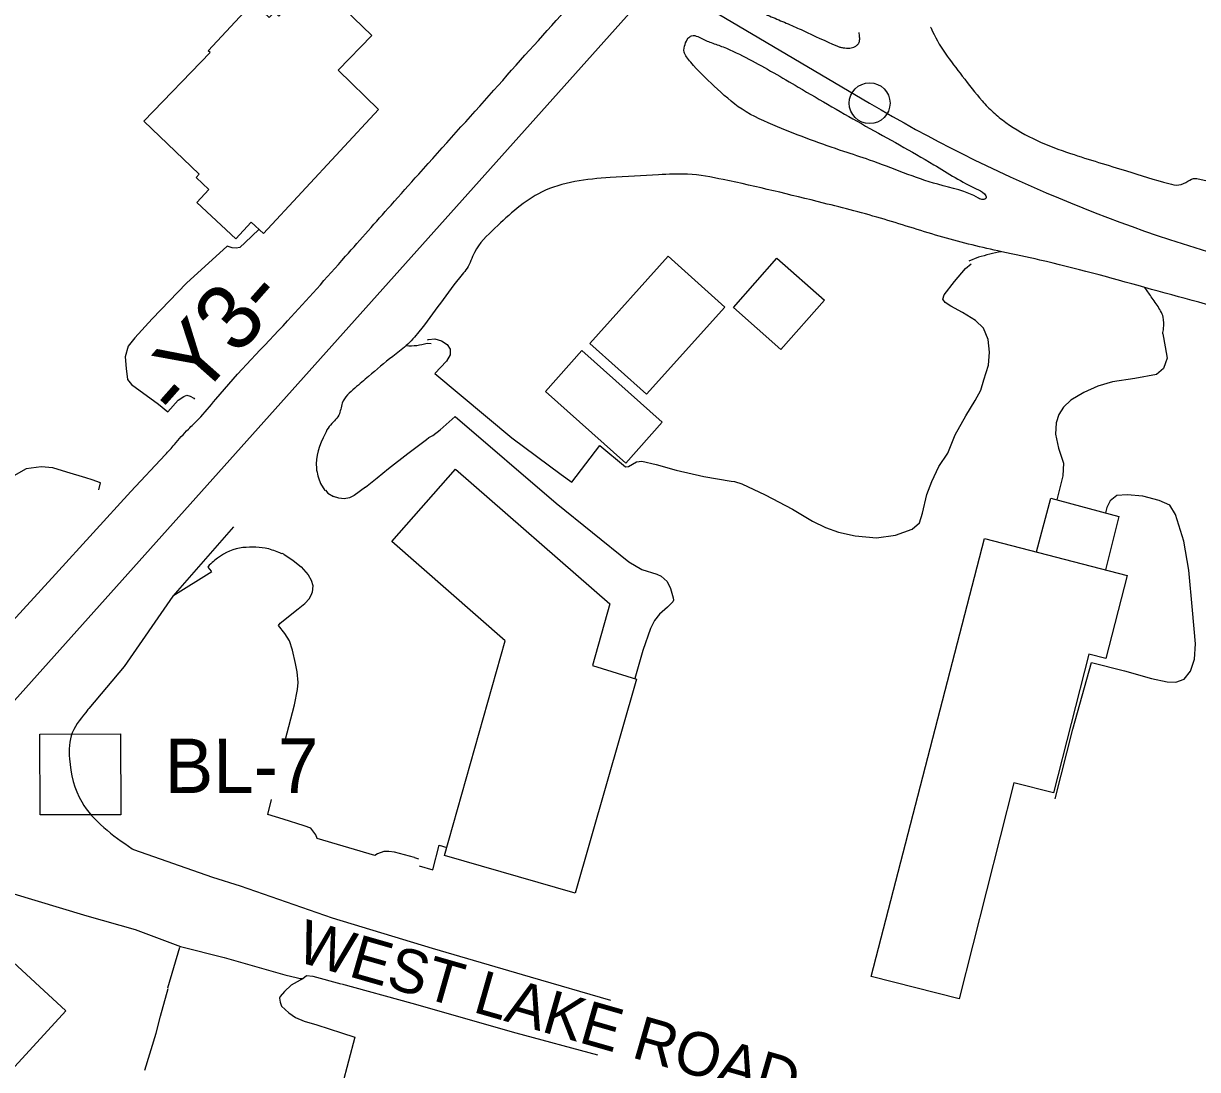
# Model space of a CAD drawing. Extents: x 2088830 to 2093930, y 861854 to 865154.
# Drawn here: x 2091682.1 to 2092113.5, y 863511.1 to 863895.4 of the extents above; entities that cross this region are included whole.
import ezdxf

# ---------------------------------------------------------------- set-up
doc = ezdxf.new("R2010")
doc.units = 0
for name, color, linetype in [('Default', 7, 'Continuous'), ('Exist Building', 7, 'Continuous'), ('Exist Building Metal Canopy', 7, 'Continuous'), ('Exist Horizontal Alignment', 7, 'Continuous'), ('Exist Horizontal Alignment Station Label', 7, 'Continuous'), ('Exist Other Culture Area Outline', 7, 'Continuous'), ('Exist Roads EOP', 7, 'Continuous'), ('Exist Roads EOP Other', 7, 'Continuous'), ('Exist Roads EOP Text', 7, 'Continuous'), ('Exist Roads Soil', 7, 'Continuous')]:
    doc.layers.add(name, color=color, linetype=linetype)

msp = doc.modelspace()

# ---------------------------------------------------------------- linework, layer by layer
at = {"layer": 'Default'}
for p, q in [((2091668.57, 863635.39), (2092319.98, 864363.19)), ((2091898.12, 863922.18), (2091993.02, 863866.1)), ((2091702.85, 863619.58), (2091702.85, 863619.58))]:
    msp.add_line(p, q, dxfattribs=at)
msp.add_lwpolyline([(2091688.1, 863634.33), (2091717.75, 863634.43), (2091717.86, 863604.73), (2091688.21, 863604.63)], close=True, dxfattribs=at)
msp.add_arc((2092280.46, 864352.52), 565, 239.4206, 255.1718, dxfattribs=at)
at = {"layer": 'Exist Building'}
for points in [[(2091812.53, 863863.75), (2091770.26, 863818.18), (2091765.75, 863822.36), (2091760.12, 863816.27), (2091745.73, 863829.61), (2091750.24, 863834.41), (2091745.59, 863838.86), (2091746.7, 863840.03), (2091726.37, 863859.45), (2091750.65, 863884.73), (2091749.93, 863885.4), (2091766.52, 863903.07), (2091772.43, 863897.53), (2091774.3, 863899.52), (2091775.9, 863898.02), (2091785.95, 863908.72), (2091787.07, 863907.67), (2091789.91, 863910.58), (2091810.11, 863890.93), (2091797.71, 863878.18)], [(2091919.05, 863809.88), (2091890.26, 863777.85), (2091911.05, 863759.16), (2091939.84, 863791.19)], [(2091958.97, 863809.2), (2091976.47, 863793.71), (2091960.45, 863775.62), (2091942.96, 863791.11)], [(2091836.79, 863589.79), (2091859.1, 863668.55), (2091817.48, 863705.04), (2091840.86, 863731.69), (2091897.5, 863682.15), (2091891.15, 863659.52), (2091907.32, 863654.52), (2091884.79, 863575.86)], [(2091993.59, 863545.26), (2092035.21, 863706.21), (2092087.71, 863692.63), (2092079.81, 863662.09), (2092073.58, 863663.69), (2092060.58, 863612.8), (2092045.99, 863616.49), (2092025.87, 863537.08)], [(2091665.32, 863562.47), (2091612.57, 863505.19), (2091635.21, 863484.35), (2091646.25, 863496.33), (2091655.98, 863487.38), (2091697.69, 863532.68)]]:
    msp.add_lwpolyline(points, close=True, dxfattribs=at)
at = {"layer": 'Exist Building Metal Canopy'}
msp.add_lwpolyline([(2091887.31, 863775.24), (2091916.83, 863748.91), (2091903.38, 863733.83), (2091873.86, 863760.16)], close=True, dxfattribs=at)
msp.add_lwpolyline([(2092054.4, 863701.24), (2092059.59, 863721), (2092084.65, 863714.28), (2092079.7, 863694.7)], dxfattribs=at)
at = {"layer": 'Exist Horizontal Alignment Station Label'}
msp.add_circle((2091993.02, 863866.1), 7.5, dxfattribs=at)
at = {"layer": 'Exist Other Culture Area Outline'}
msp.add_lwpolyline([(2091827.47, 863585.95), (2091832.54, 863584.48), (2091834.86, 863593.54), (2091837.63, 863592.74)], dxfattribs=at)
at = {"layer": 'Exist Roads EOP'}
for p, q in [((2092032.99, 863809.49), (2092029.47, 863808.1)), ((2091791.23, 863726.41), (2091792.78, 863723.88)), ((2091751.27, 863693.96), (2091736.99, 863684.95))]:
    msp.add_line(p, q, dxfattribs=at)
for points in [[(2091734.18, 863736.92), (2091721.57, 863723.4), (2091693.87, 863693.03), (2091676.72, 863674.36), (2091660.52, 863656.21), (2091640.2, 863634.61)], [(2091759.26, 863710.48), (2091736.93, 863685), (2091719.03, 863659.13), (2091706.08, 863643.77)], [(2091750.38, 863696.42), (2091749.83, 863695.62), (2091751.09, 863694.17)], [(2091721.97, 863592.19), (2091722.52, 863591.93), (2091751.6, 863581.73), (2091761.71, 863578.54), (2091795.52, 863566.8), (2091832.3, 863555.65), (2091868.27, 863545.16), (2091897.82, 863536.6)], [(2091655.69, 863579.19), (2091656.21, 863579.4), (2091656.13, 863579.68), (2091658.97, 863580.88), (2091659.28, 863581.75), (2091666.09, 863580.15), (2091666.95, 863578.98), (2091677.33, 863575.99), (2091705.32, 863567.54), (2091723.14, 863562.53), (2091739.84, 863556.32), (2091755.83, 863552.33), (2091778.96, 863545.71)], [(2091779.25, 863545.61), (2091783.78, 863544.54), (2091784.79, 863544.51), (2091786.06, 863545.62), (2091788.39, 863545.44), (2091798.68, 863542.59)], [(2091784.81, 863544.41), (2091784.75, 863544.39), (2091783.75, 863543.97)], [(2091893.11, 863516.4), (2091863.13, 863524.5), (2091824.96, 863535.32), (2091799.13, 863542.51)]]:
    msp.add_lwpolyline(points, dxfattribs=at)
msp.add_ellipse((2092048.83, 863770.86), major_axis=(-56.28, -10.97), ratio=0.721384, start_param=4.703784, end_param=4.855195, dxfattribs=at)
for points in [[(2091734.18, 863736.92), (2091737.57, 863740.74), (2091742.7, 863746.41), (2091746.39, 863749.99), (2091752.74, 863757.34), (2091779.15, 863786.15), (2091800.43, 863809.86), (2091817.14, 863828.66), (2091827.31, 863840.06), (2091854.93, 863870.83), (2091881.2, 863900.12), (2091888.17, 863907.69), (2091904.65, 863926.31), (2091929.6, 863954.75), (2091942.38, 863969.24), (2091969.89, 863999.82), (2091984.53, 864016.32), (2091999.97, 864033.43), (2092012.73, 864047.99), (2092025.65, 864062.7), (2092046.42, 864086.24), (2092066.29, 864109.17), (2092073.24, 864116), (2092075.7, 864118.27)], [(2091940.52, 863905.82), (2091946.75, 863902.64), (2091952.13, 863900.03), (2091957.58, 863897.59), (2091963.08, 863895.22), (2091965.82, 863894.02), (2091968.55, 863892.81), (2091980.94, 863887.15), (2091982.08, 863886.73), (2091983.28, 863886.46), (2091984.5, 863886.34), (2091985.11, 863886.33), (2091985.7, 863886.36), (2091987.76, 863886.97), (2091988.62, 863887.62), (2091988.95, 863888.04), (2091989.07, 863888.27), (2091989.18, 863888.52), (2091989.3, 863888.97), (2091989.36, 863890.31), (2091989.26, 863891.21), (2091989.14, 863892.1)], [(2091934.8, 863888.35), (2091932.8, 863889.15), (2091929.91, 863890.55), (2091927.6, 863890.89), (2091926.35, 863889.96), (2091925.2, 863887.71), (2091924.87, 863884.91), (2091925.75, 863883.14), (2091927.27, 863881.15), (2091935.92, 863872.36), (2091946.13, 863863.88), (2091959.14, 863857.42), (2091983.53, 863848.38), (2091993, 863845.22), (2092018.13, 863836.3), (2092033.08, 863831.22), (2092034.67, 863830.67), (2092035.87, 863831.32), (2092035.2, 863832.76), (2092032.22, 863834.64), (2092016.56, 863843.52), (2091991.56, 863857.72), (2091966.77, 863872.02), (2091948.66, 863882.32), (2091939.19, 863886.75), (2091934.8, 863888.35)], [(2092015.44, 863894.03), (2092015.59, 863893.68), (2092020.78, 863884.51), (2092027.07, 863876.03), (2092034.41, 863866.92), (2092038.45, 863862.77), (2092043.03, 863859.05), (2092054.59, 863852.38), (2092066.89, 863847.63), (2092087.45, 863841.22), (2092102.98, 863836.55), (2092106.69, 863836.06), (2092109.98, 863837.49), (2092112.72, 863838.5), (2092113.8, 863838.36), (2092114.88, 863838.1), (2092117.05, 863837.51), (2092123.9, 863835.78), (2092134.51, 863833.26), (2092139.82, 863831.98), (2092142.46, 863831.29), (2092145.09, 863830.56), (2092148.56, 863828.9), (2092151.83, 863826.8), (2092157.4, 863823.44), (2092159.85, 863822.5), (2092162.31, 863821.63), (2092167.27, 863820.07), (2092177.32, 863817.44), (2092192.54, 863813.99), (2092197.6, 863812.76), (2092205.33, 863810.83), (2092213.09, 863809.05), (2092215.67, 863809.19), (2092216.97, 863809.43), (2092218.26, 863809.49), (2092229.44, 863807.44), (2092234.76, 863805.43), (2092239.98, 863803.33), (2092250.45, 863799.3), (2092264.32, 863794.54)], [(2092264.79, 863753.35), (2092261.51, 863754.31), (2092220.59, 863764.86), (2092181.43, 863775.4), (2092144.63, 863785.3), (2092133.89, 863787.86), (2092094.14, 863798.41), (2092055.58, 863808.48), (2092041.55, 863811.54), (2092019.95, 863816.88), (2091998.39, 863823.46), (2091976.08, 863829.41), (2091939.23, 863838.04), (2091926.12, 863840.01), (2091915.42, 863839.78), (2091897.67, 863838.81), (2091872.49, 863833.46), (2091855.35, 863820.22), (2091847.81, 863811.29), (2091845.08, 863805.49), (2091843.31, 863803.2), (2091827.39, 863782.15), (2091822.71, 863777.04), (2091817.76, 863773.1), (2091808.91, 863765.73), (2091803.88, 863761.45), (2091799.23, 863755.93), (2091797.96, 863751.49), (2091794.46, 863747.35), (2091792.91, 863744.7), (2091789.71, 863731.97), (2091791.23, 863726.41)], [(2091777.12, 863700.57), (2091775.95, 863701.04), (2091770.93, 863702.64), (2091766.34, 863702.97), (2091761.42, 863702.66), (2091752.44, 863698.22), (2091750.38, 863696.42)], [(2091706.08, 863643.77), (2091705.74, 863643.32), (2091700.03, 863634.86), (2091699.01, 863625.24), (2091703.48, 863609.45), (2091721.97, 863592.19)]]:
    msp.add_spline(points, degree=3, dxfattribs=at)
at = {"layer": 'Exist Roads EOP Other'}
for p, q in [((2091825.76, 863588.95), (2091827.25, 863588.47)), ((2091735.18, 863541.1), (2091739.55, 863556.07))]:
    msp.add_line(p, q, dxfattribs=at)
for points in [[(2091768.62, 863819.7), (2091763.55, 863814.89), (2091761.58, 863813.15), (2091760.27, 863812.8), (2091758.72, 863813.01), (2091756.99, 863813.54), (2091741.95, 863799.94), (2091729.42, 863786.83), (2091722.99, 863779.87), (2091720.52, 863776.85), (2091719.51, 863772.99), (2091719.88, 863768.64), (2091720.26, 863764.58), (2091721.72, 863762.72), (2091731.7, 863755.51), (2091735.11, 863752.76), (2091738.97, 863756.97), (2091741.02, 863758.4), (2091742.11, 863758.89), (2091743.4, 863758.5), (2091744.67, 863757.75), (2091744.93, 863757.36)], [(2091832.48, 863744.09), (2091835.19, 863746.16), (2091840.74, 863750.96), (2091877.82, 863719.2), (2091904.55, 863697.67), (2091909.31, 863694.82), (2091914.77, 863693.12), (2091916.43, 863692.41), (2091918.62, 863690.44), (2091919.81, 863687.77), (2091920.83, 863684.36), (2091921.01, 863683.51), (2091920.66, 863682.93), (2091918.76, 863680.96), (2091915.78, 863678.43), (2091913.91, 863676.07), (2091912.45, 863673.16), (2091909.69, 863665.11), (2091906.7, 863654.71)], [(2091709.82, 863724.09), (2091710.43, 863726.63), (2091707.29, 863727.77), (2091704.98, 863728.48), (2091698.04, 863730.61), (2091692.89, 863732.2), (2091688.54, 863732.52), (2091683.12, 863731.81), (2091676.84, 863728.24), (2091672.3, 863728.53), (2091666.84, 863731.92), (2091655.29, 863742.21), (2091639.69, 863728.05), (2091623.47, 863710.19), (2091631.13, 863703.58), (2091632.8, 863702.2), (2091632.89, 863700.81), (2091632.16, 863698.88), (2091631.56, 863698.16), (2091640.02, 863690.43), (2091637.25, 863687.26), (2091635.22, 863686.33), (2091632.8, 863686.46), (2091631.33, 863687.59)], [(2091807.74, 863725.09), (2091812.05, 863728.54), (2091816.17, 863731.91), (2091823.36, 863737.45), (2091830.21, 863742.59), (2091831.05, 863743.26), (2091832.48, 863744.09)], [(2091793.02, 863724), (2091793.92, 863722.86), (2091796.04, 863721.6)], [(2091807.74, 863725.09), (2091803.63, 863721.95), (2091801.9, 863721.11), (2091799.97, 863720.8), (2091797.94, 863721), (2091796.04, 863721.6)], [(2091777.82, 863700.43), (2091777.18, 863700.72)], [(2091777.82, 863700.43), (2091781.22, 863698.17), (2091784.11, 863695.79), (2091786.67, 863692.84), (2091787.84, 863690.93), (2091788.36, 863688.93), (2091788.12, 863686.37)], [(2091776.44, 863675.04), (2091782.98, 863680.34), (2091785.48, 863682.37), (2091787.14, 863684.21), (2091788.01, 863685.93), (2091788.12, 863686.37)], [(2091778.22, 863631.95), (2091781.62, 863645.11), (2091782.76, 863650.72), (2091783.01, 863653.3), (2091782.68, 863657.18), (2091782.07, 863660.32), (2091781, 863665.16), (2091779.82, 863668.59), (2091778.08, 863671.31), (2091775.82, 863674.25), (2091776.44, 863675.04)], [(2091771.94, 863604.82), (2091773.2, 863610.26)], [(2091825.76, 863588.95), (2091822.12, 863589.96), (2091818.39, 863590.93), (2091816.37, 863591.17), (2091814.48, 863591.2), (2091812.13, 863590.37), (2091811.2, 863589.71), (2091790.02, 863595.97), (2091789.51, 863597.29), (2091787.63, 863599.77), (2091785.17, 863600.7), (2091777.47, 863603.1), (2091771.94, 863604.82)], [(2091783.75, 863543.97), (2091780.51, 863542.16), (2091777.95, 863539.73), (2091776.36, 863537.99), (2091776.16, 863537.34), (2091776.36, 863535.82), (2091776.91, 863534.45), (2091779.65, 863531.97), (2091782.09, 863530.24), (2091785.21, 863528.89), (2091789.92, 863527.54), (2091798.99, 863524.65), (2091803.89, 863523.03), (2091796.88, 863496.51), (2091785.94, 863499.14), (2091782.29, 863489.39), (2091791.74, 863486.74), (2091789.94, 863478.26), (2091789.88, 863477.91)], [(2091726.7, 863510.93), (2091730.81, 863524.44), (2091732.38, 863530.67), (2091735.29, 863540.89)]]:
    msp.add_lwpolyline(points, dxfattribs=at)
at = {"layer": 'Exist Roads Soil'}
for p, q in [((2092095.82, 863796), (2092094.21, 863798.34)), ((2091830.4, 863777.95), (2091831.85, 863777.83))]:
    msp.add_line(p, q, dxfattribs=at)
for points in [[(2091943.32, 863727.19), (2091946.04, 863726.31), (2091954.62, 863722.28), (2091964.64, 863717.01), (2091972.06, 863712.51), (2091976.78, 863710.19), (2091981.57, 863708.48), (2091987.66, 863707.15), (2091995.59, 863706.48), (2092002.49, 863707.42), (2092008.6, 863709.59), (2092011.35, 863712), (2092012.39, 863715.48), (2092013.99, 863722.38), (2092015.83, 863727.11), (2092018.47, 863732.59), (2092021.71, 863737.6), (2092024.44, 863744.27), (2092028.32, 863751.26), (2092031.78, 863756.88), (2092033.84, 863760.63), (2092035.03, 863764.43), (2092036.71, 863769.84), (2092037.04, 863774.64), (2092036.59, 863779.26), (2092034.87, 863783.4), (2092031.95, 863786.24), (2092027.21, 863789.25), (2092022.86, 863791.51), (2092020.84, 863792.83), (2092019.88, 863794.07), (2092020.37, 863795.66), (2092024.15, 863800.62), (2092028.24, 863805.36), (2092030.29, 863807.15)], [(2091830.54, 863779.16), (2091830.88, 863779.28), (2091833.21, 863779.57), (2091835.74, 863778.78), (2091837.74, 863777.4), (2091838.85, 863775.71), (2091838.84, 863773.72), (2091837.58, 863771.31), (2091833.21, 863766.76), (2091861.59, 863743.18), (2091879.66, 863729.65), (2091883.56, 863726.83), (2091893.82, 863740.38), (2091903.31, 863732.55), (2091904.42, 863732.64), (2091907.33, 863734.33), (2091909.36, 863734.64), (2091914.62, 863733.38), (2091921.94, 863731.27), (2091932.14, 863729.03), (2091942.13, 863727.3), (2091943.32, 863727.19)], [(2092100.73, 863781.42), (2092101.61, 863776.57), (2092102.3, 863772.38), (2092101.79, 863770.74), (2092101.06, 863768.63), (2092098.43, 863766.39), (2092090.47, 863765.02), (2092082.32, 863763.75), (2092076.93, 863762.15), (2092071.69, 863759.78), (2092066.98, 863756.96), (2092064.24, 863754.46), (2092062.56, 863751.76), (2092061.61, 863748.71), (2092061.38, 863744.52), (2092062.48, 863739.35), (2092064.22, 863733.82), (2092064.04, 863729.16), (2092061.83, 863720.4)], [(2092061.24, 863610.52), (2092067.69, 863636.13), (2092074.51, 863660.7), (2092086.73, 863657.57), (2092096.64, 863654.77), (2092102.35, 863653.53), (2092105.53, 863653.36), (2092108.63, 863654.54), (2092110.97, 863657.43), (2092112.35, 863661.86), (2092112.81, 863667.46), (2092111.64, 863679.92), (2092110.28, 863694.54), (2092108.46, 863705.27), (2092105.45, 863714.95), (2092103.33, 863718.4), (2092099.46, 863720.11), (2092093.41, 863721.79), (2092087.67, 863722.27), (2092083.91, 863721.98), (2092081.42, 863719.97), (2092080.17, 863717.61), (2092079.73, 863715.59)]]:
    msp.add_lwpolyline(points, dxfattribs=at)
msp.add_ellipse((2091824.53, 863796.28), major_axis=(19.19, 4.71), ratio=0.973683, start_param=4.389222, end_param=4.779676, dxfattribs=at)
msp.add_spline([(2092100.73, 863781.42), (2092101.02, 863783.4), (2092100.88, 863787.5), (2092098.66, 863791.9), (2092095.82, 863796)], degree=3, dxfattribs=at)

# ---------------------------------------------------------------- texts
at = {"layer": 'Default'}
msp.add_text('BL-7', height=20, rotation=0.1148, dxfattribs=at).set_placement((2091734, 863612.66))
at = {"layer": 'Exist Horizontal Alignment'}
msp.add_text('-Y3-', height=24, rotation=48.4916, dxfattribs=at).set_placement((2091739.33, 863748.94))
at = {"layer": 'Exist Roads EOP Text'}
msp.add_text('WEST LAKE ROAD', height=16, rotation=344.0088, dxfattribs=at).set_placement((2091781.66, 863551.06))

doc.saveas('drawing.dxf')
